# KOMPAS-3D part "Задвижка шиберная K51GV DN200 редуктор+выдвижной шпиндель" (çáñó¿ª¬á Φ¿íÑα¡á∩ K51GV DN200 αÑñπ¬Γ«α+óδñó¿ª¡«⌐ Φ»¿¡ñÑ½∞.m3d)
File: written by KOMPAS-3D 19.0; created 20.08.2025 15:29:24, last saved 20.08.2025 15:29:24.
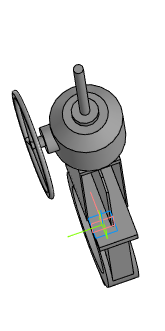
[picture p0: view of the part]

Document properties: Полное имя файла: Задвижка шиберная K51GV DN200 редуктор+выдвижной шпиндель.a3d

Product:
- Part/product: Задвижка шиберная K51GV DN200 редуктор+выдвижной шпиндель
    Масса: 58.5273

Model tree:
1. Операция без истории:1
